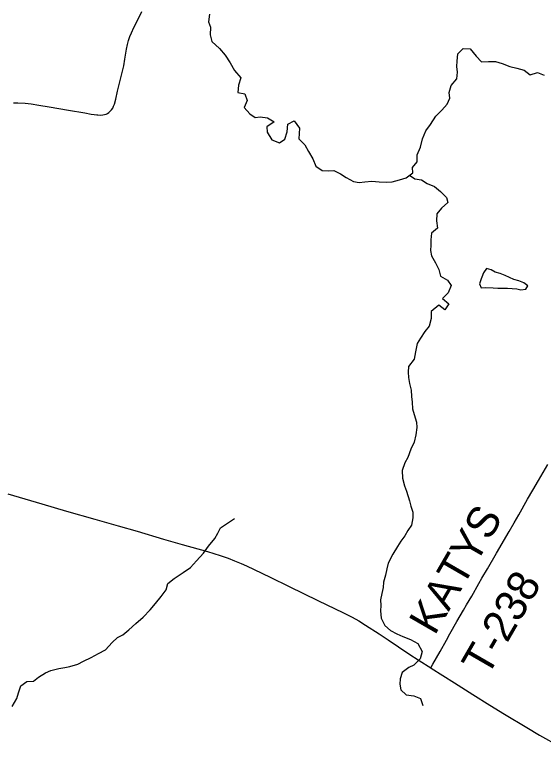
# Model space of a CAD drawing. Extents: x 0 to 34, y 0 to 22.
# Drawn here: x 3.738 to 4.698, y 16.326 to 17.655 of the extents above; entities that cross this region are included whole.
import ezdxf

# ---------------------------------------------------------------- set-up
doc = ezdxf.new("R2010")
doc.units = 0
for name, color, linetype in [('GM_X_County_Road', 7, 'Continuous'), ('GM_X_Minor_Lake', 7, 'Continuous'), ('GM_X_Minor_River', 7, 'Continuous'), ('GM_X_State_Route', 7, 'Continuous'), ('GM_X_Township_Road', 7, 'Continuous'), ('GM_X_Township_Road_Text', 7, 'Continuous')]:
    doc.layers.add(name, color=color, linetype=linetype)

msp = doc.modelspace()

# ---------------------------------------------------------------- linework, layer by layer
at = {"layer": 'GM_X_County_Road'}
msp.add_lwpolyline([(3.736, 17.4953), (3.7434, 17.4952), (3.7571, 17.4943), (3.7676, 17.4931), (3.7818, 17.4911), (3.8008, 17.488), (3.8356, 17.4818), (3.865, 17.4767), (3.8766, 17.4747), (3.8821, 17.4739), (3.887, 17.4734), (3.8888, 17.4732), (3.8931, 17.4729), (3.8979, 17.4731), (3.9009, 17.4736), (3.9037, 17.4745), (3.9064, 17.4758), (3.9088, 17.4775), (3.9115, 17.4799), (3.9138, 17.4826), (3.9158, 17.4856), (3.9174, 17.4889), (3.9189, 17.4929), (3.9213, 17.5018), (3.9248, 17.5162), (3.9324, 17.5476), (3.9359, 17.5621), (3.9381, 17.5743), (3.941, 17.5926), (3.9428, 17.6012), (3.9447, 17.6084), (3.9472, 17.6155), (3.95, 17.6224), (3.9545, 17.632), (3.96, 17.6431), (3.9688, 17.6607)], dxfattribs=at)
at = {"layer": 'GM_X_Minor_Lake'}
for points in [[(4.6678, 17.1598), (4.6697, 17.1629), (4.6619, 17.1684), (4.6532, 17.1716), (4.6441, 17.1741), (4.6359, 17.178), (4.628, 17.1816), (4.6193, 17.1848), (4.6102, 17.1877), (4.6027, 17.1916), (4.5944, 17.194), (4.5889, 17.1862), (4.5861, 17.1783), (4.5849, 17.1756)], [(4.5849, 17.1756), (4.5817, 17.1666), (4.5846, 17.1589), (4.5922, 17.1595), (4.6066, 17.1592), (4.615, 17.1583), (4.6324, 17.1587), (4.6408, 17.1578), (4.6495, 17.1573), (4.657, 17.1552), (4.6658, 17.1565), (4.6678, 17.1598)]]:
    msp.add_lwpolyline(points, dxfattribs=at)
at = {"layer": 'GM_X_Minor_River'}
for points in [[(4.0914, 17.6559), (4.0896, 17.6423), (4.0932, 17.6323), (4.093, 17.6187), (4.0958, 17.6065), (4.1096, 17.594), (4.1199, 17.5817), (4.1288, 17.5675), (4.1372, 17.5536), (4.1484, 17.5405), (4.1439, 17.5273), (4.1429, 17.514), (4.1558, 17.5115), (4.1597, 17.4992), (4.1545, 17.4864), (4.1645, 17.4748), (4.1743, 17.4686), (4.1838, 17.4695), (4.197, 17.4677), (4.2087, 17.4603), (4.1956, 17.4514), (4.1961, 17.4419), (4.2046, 17.4281), (4.2185, 17.4221), (4.2281, 17.4288), (4.2326, 17.4424), (4.234, 17.456), (4.2455, 17.4622), (4.2551, 17.4491), (4.2546, 17.4396), (4.254, 17.4294), (4.2648, 17.4189), (4.2714, 17.4067), (4.2791, 17.3932), (4.2845, 17.3802), (4.2961, 17.372), (4.3067, 17.3714), (4.317, 17.372), (4.3294, 17.366), (4.3399, 17.3593), (4.3531, 17.3522), (4.3633, 17.3505), (4.3735, 17.3515), (4.3861, 17.3527), (4.3997, 17.3513), (4.4123, 17.3507), (4.4229, 17.3516), (4.4363, 17.3551), (4.4485, 17.3591), (4.4604, 17.368), (4.4599, 17.3778), (4.4684, 17.3879), (4.4683, 17.4008), (4.4743, 17.4144), (4.4784, 17.4295), (4.484, 17.4442), (4.4926, 17.4554), (4.5023, 17.4708), (4.5132, 17.482), (4.5229, 17.4924), (4.5277, 17.5037), (4.5264, 17.5136), (4.5304, 17.5264), (4.5405, 17.5388)], [(4.5405, 17.5388), (4.5419, 17.5509), (4.5406, 17.5608), (4.5412, 17.571), (4.5426, 17.5839), (4.5523, 17.5936), (4.5648, 17.5933), (4.5755, 17.5798), (4.5852, 17.5694), (4.5981, 17.5699), (4.6106, 17.57), (4.6231, 17.5667), (4.6366, 17.5608), (4.6495, 17.5579), (4.6627, 17.5542), (4.6739, 17.546), (4.6869, 17.5499), (4.699, 17.5455)], [(4.4544, 17.3635), (4.464, 17.3569), (4.4765, 17.3551), (4.4866, 17.3485), (4.4998, 17.3429), (4.511, 17.3343), (4.5218, 17.3234), (4.5243, 17.3139), (4.5127, 17.3035), (4.5045, 17.2934), (4.5035, 17.2809), (4.5055, 17.2676), (4.4943, 17.2583), (4.4933, 17.2462), (4.4931, 17.2363), (4.4926, 17.2268), (4.4943, 17.2169), (4.5016, 17.2046), (4.5078, 17.1923), (4.5106, 17.1805), (4.5234, 17.1727), (4.5304, 17.163), (4.5248, 17.1502), (4.5147, 17.1398), (4.5259, 17.1301), (4.5189, 17.1192), (4.5077, 17.1278), (4.494, 17.1163)], [(4.494, 17.1163), (4.4941, 17.1031), (4.4901, 17.0895), (4.4827, 17.0798), (4.4748, 17.0674), (4.4686, 17.0577), (4.4656, 17.0429), (4.4631, 17.0297), (4.4529, 17.0162), (4.4524, 17.006), (4.4525, 16.9965), (4.4546, 16.9855), (4.4574, 16.9729), (4.4583, 16.9619), (4.4592, 16.9516), (4.4601, 16.9395), (4.4633, 16.9292), (4.4675, 16.915), (4.4677, 16.9056), (4.4659, 16.8919), (4.463, 16.8787), (4.4571, 16.8663), (4.4518, 16.8509), (4.4463, 16.8411), (4.4411, 16.8272), (4.442, 16.8135), (4.4455, 16.7994), (4.4491, 16.7895), (4.4544, 16.7723), (4.4572, 16.7627), (4.4604, 16.7517), (4.4609, 16.7414), (4.4584, 16.7282), (4.4518, 16.7185), (4.4459, 16.7087), (4.4389, 16.699), (4.433, 16.6892), (4.4244, 16.6754), (4.4161, 16.6592), (4.4132, 16.649), (4.4111, 16.6373), (4.4074, 16.6245), (4.4068, 16.615), (4.4043, 16.6041), (4.4022, 16.5924), (4.4024, 16.5821), (4.4022, 16.5726), (4.403, 16.5593), (4.41, 16.5455), (4.42, 16.5366), (4.4316, 16.5307), (4.4425, 16.5256), (4.4564, 16.5203), (4.4699, 16.5129), (4.4776, 16.4987), (4.4739, 16.4855), (4.4627, 16.4739), (4.4531, 16.4696), (4.4412, 16.4603), (4.4375, 16.449), (4.4373, 16.4392), (4.439, 16.4289), (4.4487, 16.4196), (4.4623, 16.4182), (4.4747, 16.4134), (4.479, 16.4008)], [(3.7333, 16.3984), (3.742, 16.4131), (3.7448, 16.4233), (3.7489, 16.4365), (3.76, 16.4438), (3.7718, 16.4447), (3.7814, 16.4517), (3.7941, 16.4598), (3.8036, 16.4638), (3.8181, 16.4677), (3.8288, 16.4698), (3.8383, 16.4715), (3.8524, 16.4758), (3.8627, 16.4812), (3.8765, 16.4878), (3.8903, 16.4951), (3.9025, 16.5017), (3.9149, 16.5151), (3.9246, 16.5237), (3.9345, 16.5291), (3.945, 16.538), (3.9581, 16.5492), (3.9712, 16.561), (3.984, 16.5745), (3.9937, 16.5856), (4.0041, 16.5983), (4.0131, 16.6103), (4.016, 16.622), (4.0275, 16.6309), (4.0437, 16.6423), (4.0568, 16.6512), (4.068, 16.6635), (4.0804, 16.6769), (4.0897, 16.6896), (4.1014, 16.7038), (4.1069, 16.7135), (4.1117, 16.7233), (4.124, 16.7318), (4.137, 16.7402)]]:
    msp.add_lwpolyline(points, dxfattribs=at)
at = {"layer": 'GM_X_State_Route'}
msp.add_lwpolyline([(3.7252, 16.7851), (3.7873, 16.767), (3.8319, 16.7537), (3.8833, 16.739), (3.9256, 16.7268), (3.9603, 16.7169), (4.0079, 16.7028), (4.042, 16.693), (4.088, 16.6799), (4.1111, 16.6731), (4.1255, 16.668), (4.1369, 16.6635), (4.149, 16.6584), (4.1587, 16.6539), (4.1726, 16.6473), (4.2018, 16.6334), (4.2359, 16.6169), (4.2884, 16.5914), (4.3349, 16.569), (4.3504, 16.5612), (4.3624, 16.5544), (4.375, 16.5464), (4.3995, 16.5306), (4.4156, 16.52), (4.4531, 16.4945), (4.4724, 16.482), (4.4932, 16.4688), (4.4939, 16.4684), (4.5364, 16.4414), (4.5693, 16.4203), (4.6004, 16.4009), (4.6269, 16.3847), (4.6674, 16.3605), (4.6904, 16.3469), (4.7272, 16.3263)], dxfattribs=at)
at = {"layer": 'GM_X_Township_Road'}
msp.add_lwpolyline([(4.4932, 16.4688), (4.4971, 16.4757), (4.51, 16.4984), (4.5215, 16.519), (4.5281, 16.5309), (4.5408, 16.553), (4.5528, 16.5734), (4.5583, 16.5831), (4.5675, 16.5993), (4.5805, 16.6219), (4.586, 16.6316), (4.5961, 16.6488), (4.6127, 16.6772), (4.6353, 16.7166), (4.6444, 16.7321), (4.6528, 16.7466), (4.6691, 16.7752), (4.6785, 16.7913), (4.6889, 16.809), (4.7059, 16.838)], dxfattribs=at)

# ---------------------------------------------------------------- texts
at = {"layer": 'GM_X_Township_Road_Text'}
for s, rotation, p in [('KATYS', 59.9767, (4.5003, 16.5262)), ('T-238', 59.9238, (4.5958, 16.4507))]:
    msp.add_text(s, height=0.05682, rotation=rotation, dxfattribs=at).set_placement(p)

doc.saveas('drawing.dxf')
